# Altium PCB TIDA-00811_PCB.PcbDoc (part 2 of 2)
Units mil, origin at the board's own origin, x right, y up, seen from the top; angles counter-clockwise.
Board outline 2165.35 x 1968.5 mil, 2 copper layers (Top Layer, Bottom Layer), stack 62 mil thick; 184 components, 89 nets, 461 pads, 152 vias.
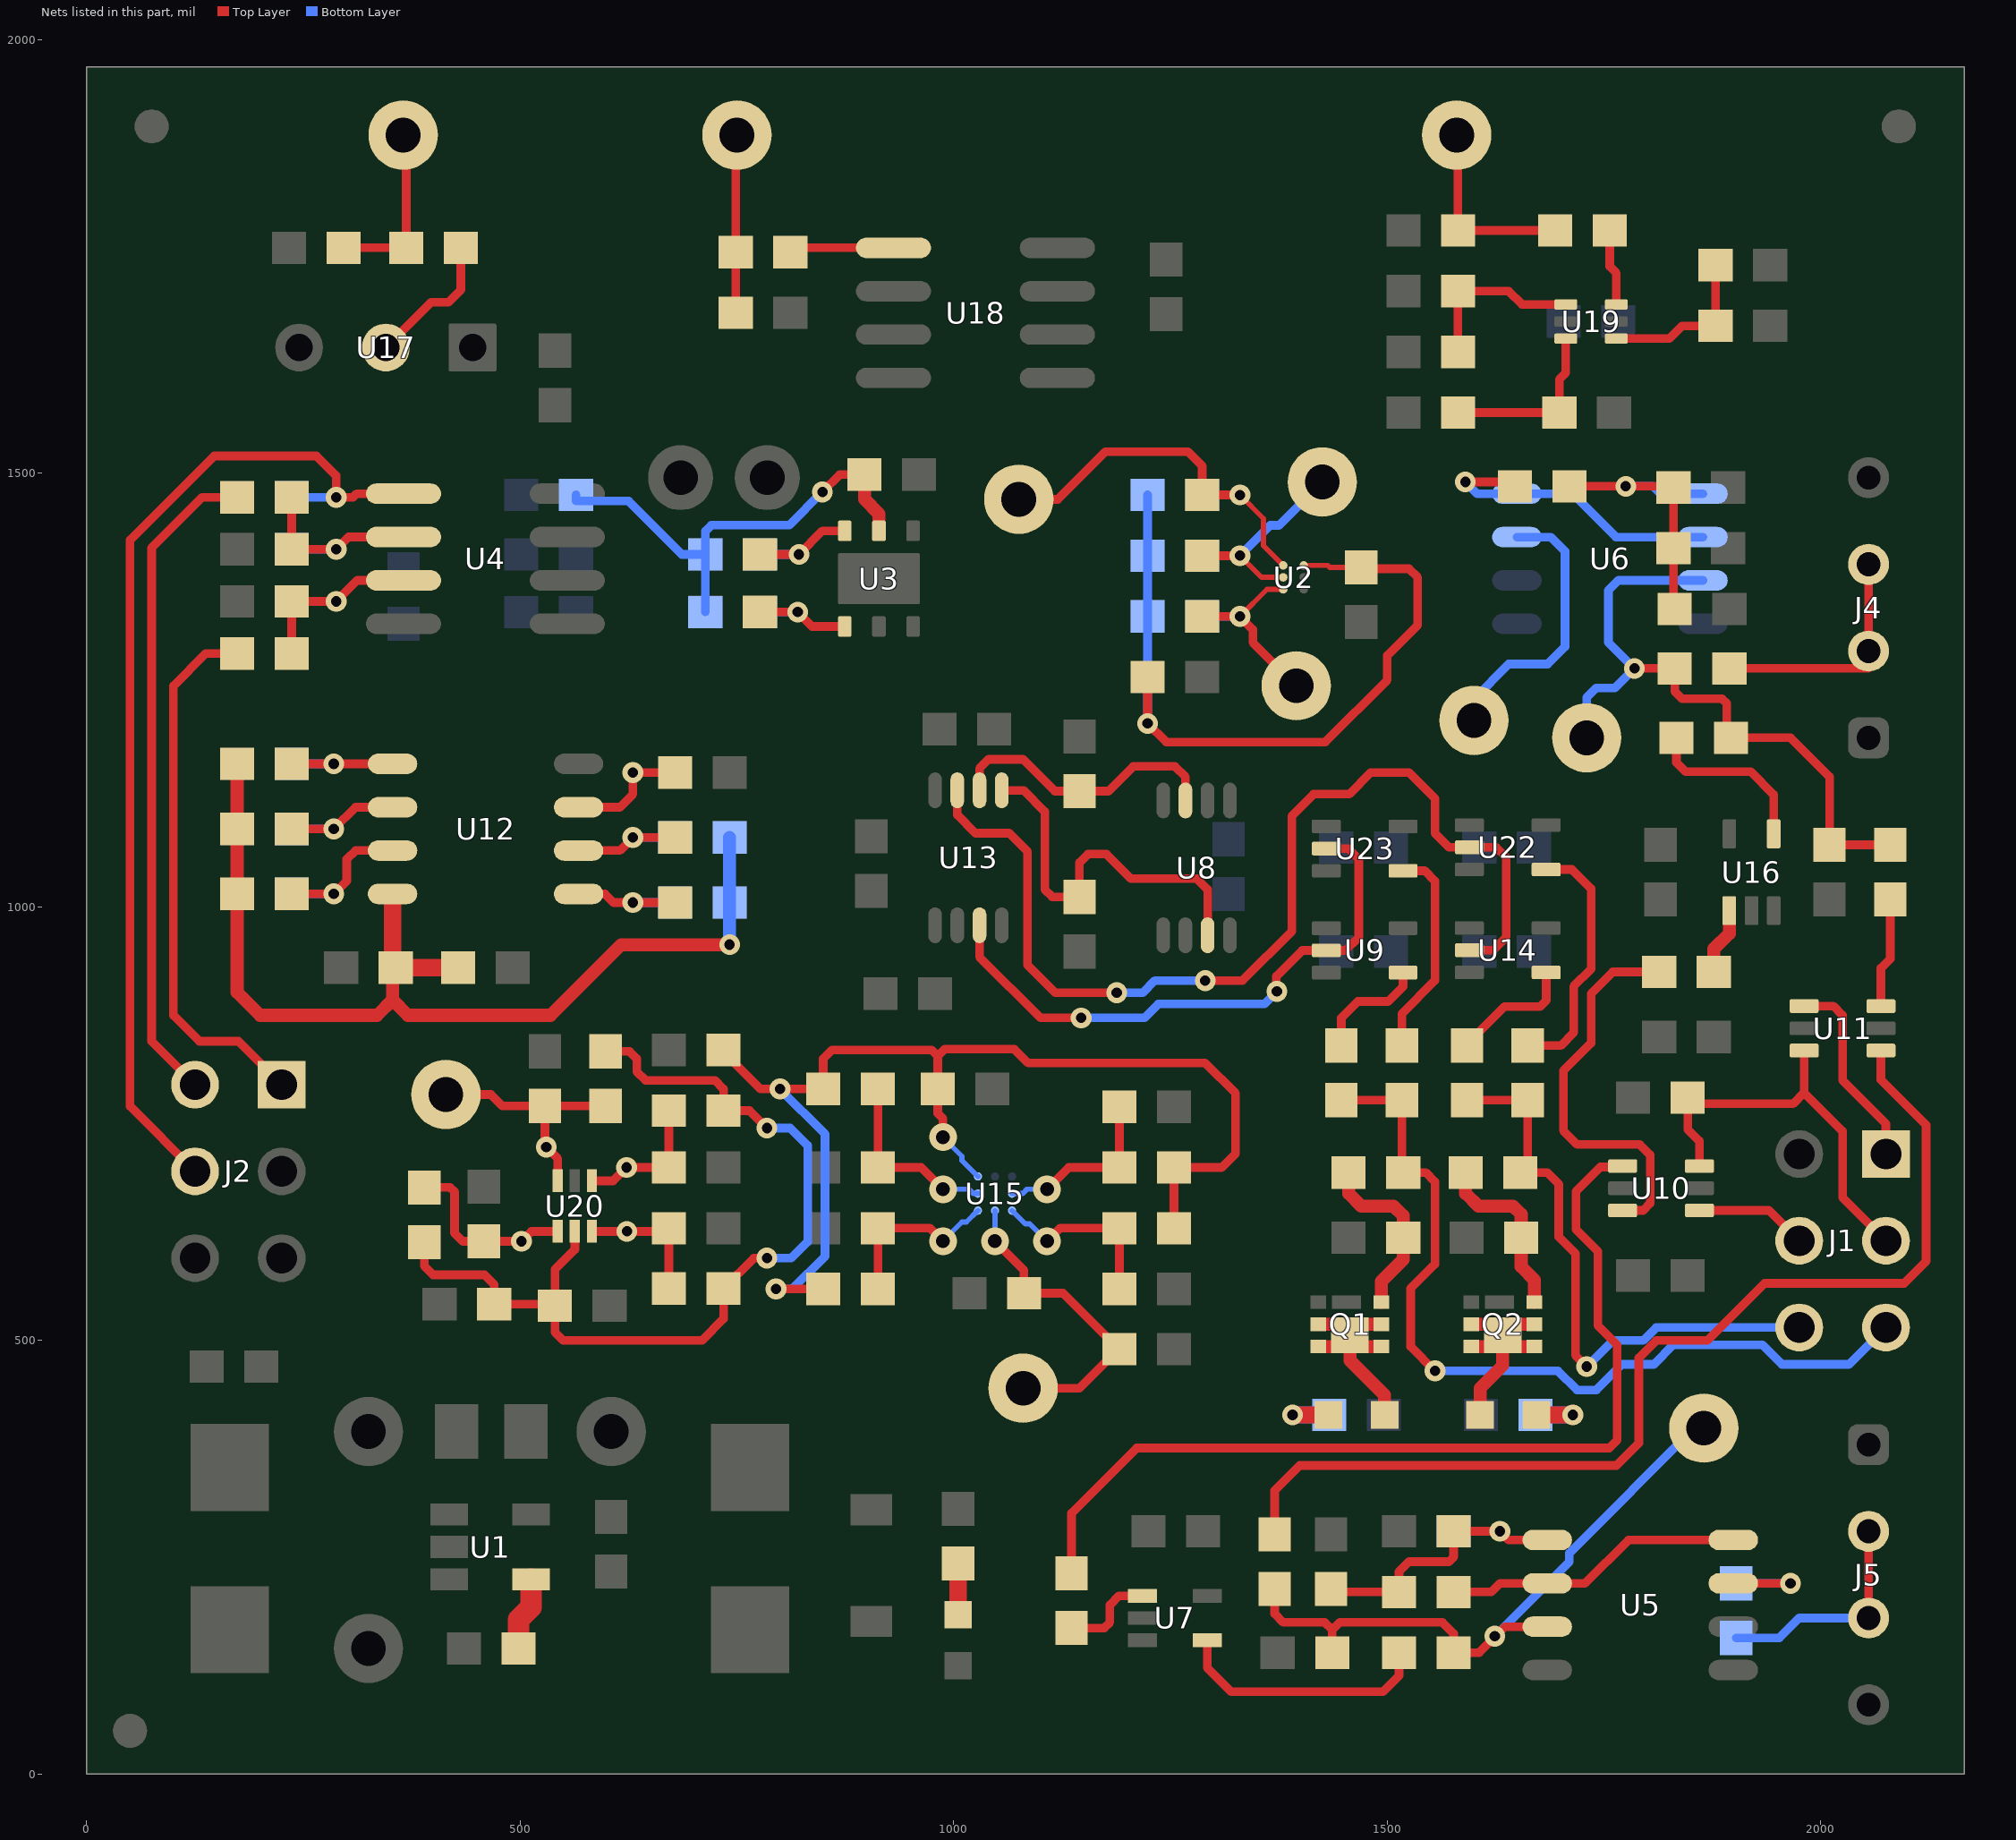
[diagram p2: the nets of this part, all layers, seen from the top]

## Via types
v1: diameter 24, hole 12, Top Layer to Bottom Layer, tented both sides, 140 vias
v2: diameter 32, hole 16, Top Layer to Bottom Layer, tented both sides, 8 vias
v3: diameter 19.68, hole 7.87, Top Layer to Bottom Layer, 4 vias

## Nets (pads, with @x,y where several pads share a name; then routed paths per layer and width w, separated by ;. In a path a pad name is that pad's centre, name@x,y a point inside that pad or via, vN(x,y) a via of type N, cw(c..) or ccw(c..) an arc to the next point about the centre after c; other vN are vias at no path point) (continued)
MCU_EN: J2.4 R3.1 U4.5 | length 1202
  Top Layer w10: J2.4@125,695 50,770 50,1423 147,1520 265,1520 287.77,1497.23 v1(287.77,1472.27) 307.27,1472.27 311.5,1476.5 U4.5@365.36,1476.5
  Bottom Layer w10: R3.1@236.51,1472.27 v1(287.77,1472.27)
MCU_INT: J1.5 R85.1 R109.2 R110.2 | length 1014
  Top Layer w10: R109.2@1446.88,777.17 R110.2@1516.88,777.17 1516.88,695.16 R85.1@1518.37,693.66 1544.34,693.66 1555,683 1555,588 1527,560 1527,493 v1(1555,465)
  Bottom Layer w10: v1(1555,465) 1696.82,465 1718.82,443 1741.18,443 1770.62,472.44 1807.44,472.44 1830,495 1932.44,495 1955,472.44 2032.44,472.44 J1.5@2075,515
MCU_INT1: J1.6 R86.1 R107.2 R108.2 | length 691.3
  Top Layer w10: R107.2@1591.88,777.17 R108.2@1661.88,777.17 R86.1@1661.88,695.16 ; R86.1@1651.88,695.16 R86.1@1653.37,693.66 1684.34,693.66 1697.69,680.32 1697.69,619.67 1717,600.35 1717,483 v1(1730,470)
  Bottom Layer w10: v1(1730,470) 1760,500 1795,500 1810,515 J1.6@1975,515
MCU_SCL: J2.1 R8.2 | length 627.1
  Top Layer w10: R8.2@173.52,1292.27 137.27,1292.27 100,1255 100,875 130,845 175,845 J2.1@225,795
MCU_SDA: J2.2 R9.2 | length 762.4
  Top Layer w10: J2.2@125,795 75,845 75,1414 133.27,1472.27 R9.2@173.52,1472.27
NetC5_2: C5.2 R20.1 R21.2 R22.2 R23.2 U2.C1 | length 902.1
  Top Layer w6: U2.C1@1403.62,1393.78 1431.22,1393.78 1433.5,1391.5 C5.2@1470,1391.5
  Top Layer w10: R20.1@1223.5,1265 v1(1223.5,1211.5) 1245,1190 1428.43,1190 1500,1261.57 1500,1290 1535,1325 1535,1380 1525,1390 1471.5,1390 C5.2@1470,1391.5
  Bottom Layer w10: v1(1223.5,1211.5) R21.2@1223.5,1335 R23.2@1223.5,1405 R22.2@1223.5,1475
NetC6_1: C6.1 U1.4 | length 85.5
  Top Layer w25: C6.1@498.16,145 498.16,178.16 512.4,192.4 U1.4@512.4,224.6
NetC7_2: C7.2 R15.2 R16.2 R77.1 U3.5 | length 557.4
  Top Layer w10: v1(848.5,1478.5) 868.5,1498.5 C7.2@897,1498.5
  Top Layer w15: C7.2@897,1498.5 897,1469.99 913.69,1453.3 U3.5@913.69,1433.61
  Bottom Layer w10: R77.1@564.34,1475 564.34,1468 625,1468 686.5,1406.5 R15.2@713.5,1406.5 ; R16.2@713.5,1340 R15.2@713.5,1406.5 ; v1(848.5,1478.5) 810.2,1440.2 720.2,1440.2 713.5,1433.5 R15.2@713.5,1406.5
NetC9_1: C9.1 C11.2 R10.1 R87.2 U5.1 | length 368.7
  Top Layer w10: C9.1@1435,213.5 1438.5,210 R10.1@1513.5,210 1513.5,233.5 1525,245 1571.2,245 1576.5,250.3 C11.2@1576.5,280 v1(1630,280) 1640,270 U5.1@1684.43,270
  Bottom Layer w10: R87.2@1576.5,280 v1(1630,280)
NetC10_1: C10.1 C12.2 R11.1 R88.2 U6.1 | length 353.8
  Top Layer w10: R11.1@1710,1485 v1(1775,1485) 1828.56,1485 R88.2@1830.02,1483.54 C12.2@1830.02,1413.54 1830.02,1345.04 C10.1@1831.51,1343.54
  Bottom Layer w10: v1(1775,1485) 1806.46,1485 1815,1476.46 U6.1@1864,1476.46
NetC18_2: C18.2 R28.1 R29.2 R30.2 R31.2 R32.2 R33.2 U12.8 | length 1214
  Top Layer w15: R31.2@173.5,1165 R30.2@173.5,1090 R29.2@173.5,1015 173.5,901.5 200,875 335,875 352.72,892.72 ; C18.2@352.72,933.78 352.72,892.72 ; v1(741.5,956.5) 616.5,956.5 535,875 370.43,875 352.72,892.72
  Top Layer w20: U12.8@352.72,1015 352.72,933.78 C18.2@356.5,930 R28.1@428.5,930
  Bottom Layer w15: v1(741.5,956.5) R33.2@741.5,1005 R32.2@741.5,1080
NetC23_2: C23.2 R53.2 R54.2 R68.2 R69.2 R70.1 U15.A3 | length 1390.1
  Top Layer w10: R70.1@735.03,831.94 776.97,790 v1(799.53,790) R53.2@849.54,790 849.54,825.01 859.54,835.01 974.52,835.01 981.53,828 ; v1(795.03,559.5) R54.2@849.54,559.5 ; v2(987.53,734.5) 987.53,756 981.53,762 C23.2@981.53,790 981.53,828 ; R69.2@1254.03,629.5 R68.2@1254.03,699.5 1309.03,699.5 1325,715.47 1325,758.08 ; 1325,780.92 1325,785 1290,820 1086,820 1070,836 989.53,836 981.53,828 ; 1325.03,758.11 1325.03,780.89
  Bottom Layer w6: v2(987.53,734.5) 1009.53,712.5 1009.53,707.5 U15.A3@1027.85,689.18
  Bottom Layer w10: v1(795.03,559.5) 814.03,559.5 851.53,597 851.53,738 v1(799.53,790)
NetC24_2: C24.2 R47.2 TP13.1 | length 203.5
  Top Layer w10: C24.2@296.5,1760 R47.2@368.5,1760 368.5,1886.5 TP13.1@365,1890
NetC26_2: C26.2 R48.2 TP14.1 | length 205.6
  Top Layer w10: C26.2@748.5,1685 R48.2@748.5,1755 748.5,1888.5 TP14.1@750,1890
NetC28_2: C28.2 R52.2 TP16.1 | length 222.6
  Top Layer w10: TP16.1@1580,1890 1581.5,1888.5 C28.2@1581.5,1780 R52.2@1693.5,1780
NetC29_1: C29.1 Q1.3 R85.2 | length 207.7
  Top Layer w15: R85.2@1455.38,693.66 1455.38,669.62 1470,655 1507.2,655 1518.37,643.83 C29.1@1518.37,618.66 1518.37,593.37 1493.2,568.2 Q1.3@1493.2,544.25
NetC30_1: C30.1 Q2.3 R86.2 | length 205.6
  Top Layer w15: R86.2@1590.38,693.66 1590.38,669.62 1605,655 1645,655 1654.4,645.6 C30.1@1654.4,618.66 1654.4,585.12 1669.52,570 Q2.3@1669.52,544.25
NetC31_2: C31.2 R90.1 R91.2 R94.2 R95.2 R98.2 U20.5 | length 1111.8
  Top Layer w10: R98.2@389.53,613.5 389.53,585.64 399.53,575.64 458.89,575.64 470.03,564.5 R90.1@470.03,541.94 538.1,541.94 C31.2@540.04,540 ; U20.5@563.03,625.87 563.03,605 540.04,582.01 C31.2@540.04,540 ; R91.2@598.53,833.44 626.09,833.44 634.53,825 634.53,809.85 644.38,800 724.53,800 734.53,790 R95.2@734.53,765 764.53,765 v1(784.53,745) ; v1(784.53,595) 769.53,595 R94.2@734.53,560 734.53,525 709.53,500 549.53,500 540.04,509.49 C31.2@540.04,540
  Bottom Layer w10: v1(784.53,595) 812.53,595 831.53,614 831.53,724.77 811.3,745 v1(784.53,745)
NetD2_1: D2.1 R1.1 | length 59
  Top Layer w20: D2.1@1005,184.06 R1.1@1005,243.03
NetD3_1: D3.1 Q1.1 Q1.2 Q1.5 Q1.6 Q1.8 | length 274.7
  Top Layer w15: Q1.6@1420.56,493.07 1444.08,493.07 Q1.8@1456.88,505.87 ; Q1.5@1420.56,518.66 1444.08,518.66 Q1.8@1456.88,505.87 ; Q1.1@1493.2,493.07 1469.67,493.07 Q1.8@1456.88,505.87 ; Q1.2@1493.2,518.66 1469.67,518.66 Q1.8@1456.88,505.87 ; D3.1@1496.9,414.25 1496.9,437.1 1456.88,477.12 Q1.8@1456.88,505.87
NetD3_2: D3.2 R83.1 | length 83.4
  Top Layer w20: v1(1390.75,414.25) D3.2@1431.94,414.25
  Bottom Layer w20: v1(1390.75,414.25) R83.1@1432.92,414.25
NetD4_1: D4.1 Q2.1 Q2.2 Q2.5 Q2.6 Q2.8 | length 264.5
  Top Layer w15: Q2.6@1596.88,493.07 1620.4,493.07 Q2.8@1633.2,505.87 ; Q2.5@1596.88,518.66 1620.4,518.66 Q2.8@1633.2,505.87 ; D4.1@1606.94,414.25 1606.94,444.94 1633.2,471.2 Q2.8@1633.2,495 ; Q2.1@1669.52,493.07 1635.13,493.07 Q2.8@1633.2,495 ; Q2.2@1669.52,518.66 1645.99,518.66 Q2.8@1633.2,505.87 ; Q2.8@1633.2,495 Q2.8@1633.2,505.87
NetD4_2: D4.2 R84.1 | length 83.4
  Top Layer w20: D4.2@1672.88,414.25 v1(1714.07,414.25)
  Bottom Layer w20: R84.1@1671.9,414.25 v1(1714.07,414.25)
NetJ4_2: J4.2 J4.3 R80.1 | length 260.5
  Top Layer w10: R80.1@1894.5,1275 2055,1275 J4.2@2055,1295 J4.3@2055,1375
NetJ5_2: J5.2 J5.3 R81.2 | length 262.2
  Top Layer w10: J5.3@2055,180 J5.2@2055,280
  Bottom Layer w10: R81.2@1902.28,157.01 1952.01,157.01 1975,180 J5.3@2055,180
NetR2_1: R2.1 U8.7 U13.5 | length 454.7
  Top Layer w10: U13.5@1055.28,1134.41 1080.59,1134.41 1105,1110 1105,1020 1113.5,1011.5 R2.1@1145,1011.5 1145,1051 1155,1061 1176,1061 1204.5,1032.5 1280.5,1032.5 1292.8,1020.2 U8.7@1292.8,967.24
NetR6_1: R6.1 R8.1 R73.1 U4.7 | length 250.1
  Top Layer w10: R8.1@236.51,1292.27 R73.1@236.51,1352.27 v1(287.77,1352.27) 312.01,1376.5 U4.7@365.36,1376.5
  Bottom Layer w10: R6.1@236.51,1352.27 v1(287.77,1352.27)
NetR7_1: R7.1 R9.1 R72.1 U4.6 | length 246
  Top Layer w10: R9.1@236.51,1472.27 R72.1@236.51,1412.27 v1(287.77,1412.27) 302.01,1426.5 U4.6@365.36,1426.5
  Bottom Layer w10: R7.1@236.51,1412.27 v1(287.77,1412.27)
NetR10_2: R10.2 U5.2 U5.8 | length 347.4
  Top Layer w10: R10.2@1576.5,210 1620,210 1630,220 U5.2@1684.43,220 1728,220 1778,270 U5.8@1899,270
NetR11_2: R11.2 U6.2 U6.8 | length 359.4
  Top Layer w10: v1(1590,1490) 1642.01,1490 R11.2@1647.01,1485
  Bottom Layer w10: v1(1590,1490) 1603.54,1476.46 U6.8@1649.43,1476.46 1713.54,1476.46 1763.54,1426.46 U6.2@1864,1426.46
NetR12_1: R12.1 R13.2 R14.2 TP11.1 U5.3 | length 766.7
  Top Layer w10: R14.2@1370,213.5 1370,185 1380,175 1427.99,175 1436.5,166.5 ; R12.1@1436.5,140 1436.5,166.5 ; U5.3@1684.43,170 1636,170 1606,140 R13.2@1576.5,140 1576.5,162.05 1563.54,175 1445,175 1436.5,166.5
  Bottom Layer w10: v1(1624,159) 1710,245 1710,255 1854,399 TP11.1@1865,399
NetR13_1: R13.1 U7.4 | length 298.5
  Top Layer w10: U7.4@1292.4,154.41 1292.4,122.6 1320,95 1495,95 1513.5,113.5 R13.1@1513.5,140
NetR15_1: R15.1 R17.1 U3.6 | length 154.1
  Top Layer w10: R17.1@776.5,1406.57 776.56,1406.5 v1(821.5,1406.5) 848.61,1433.61 U3.6@874.32,1433.61
  Bottom Layer w10: R15.1@776.5,1406.5 v1(821.5,1406.5)
NetR16_1: R16.1 R18.1 U3.1 | length 148.2
  Top Layer w10: R18.1@776.5,1340.07 776.56,1340 v1(820,1340) 836.62,1323.38 U3.1@874.32,1323.38
  Bottom Layer w10: R16.1@776.5,1340 v1(820,1340)
NetR19_2: R19.2 U8.3 U13.6 | length 326.1
  Top Layer w10: U13.6@1029.69,1134.41 1029.69,1159.69 1040.08,1170.08 1079.92,1170.08 1116.5,1133.5 R19.2@1145,1133.5 1178.5,1133.5 1207,1162 1255,1162 1267.2,1149.8 U8.3@1267.2,1122.76
NetR21_1: R21.1 R24.1 TP7.1 U2.A2 | length 256.9
  Top Layer w6: v1(1330,1335) 1361.22,1366.22 U2.A2@1380,1366.22
  Top Layer w10: R24.1@1286.5,1335 v1(1330,1335) 1345,1320 1345,1305 TP7.1@1395,1255
  Bottom Layer w10: R21.1@1286.5,1335 v1(1330,1335)
NetR22_1: R22.1 R25.1 TP5.1 U2.C2 | length 463.6
  Top Layer w6: v1(1330,1475) 1357.22,1447.78 1357.22,1416.56 U2.C2@1380,1393.78
  Top Layer w10: TP5.1@1075,1470 1120,1470 1175,1525 1270,1525 1286.5,1508.5 R25.1@1286.5,1475 v1(1330,1475)
  Bottom Layer w10: R22.1@1286.5,1475 v1(1330,1475)
NetR23_1: R23.1 R26.1 TP9.1 U2.B2 | length 277.6
  Top Layer w6: v1(1330,1405) 1355,1380 U2.B2@1380,1380
  Top Layer w10: R26.1@1286.5,1405 v1(1330,1405)
  Bottom Layer w10: R23.1@1286.5,1405 v1(1330,1405) 1365,1440 1375,1440 TP9.1@1425,1490
NetR29_1: R29.1 R34.1 U12.7 | length 200.1
  Top Layer w10: R29.1@236.5,1015 v1(285,1015) 300,1030 300,1055 310,1065 U12.7@352.72,1065
  Bottom Layer w10: R34.1@236.5,1015 v1(285,1015)
NetR30_1: R30.1 R35.1 U12.6 | length 175.1
  Top Layer w10: R30.1@236.5,1090 v1(285,1090) 310,1115 U12.6@352.72,1115
  Bottom Layer w10: R35.1@236.5,1090 v1(285,1090)
NetR31_1: R31.1 R39.1 U12.5 | length 164.7
  Top Layer w10: R31.1@236.5,1165 v1(285,1165) U12.5@352.72,1165
  Bottom Layer w10: R39.1@236.5,1165 v1(285,1165)
NetR32_1: R32.1 R41.1 U12.2 | length 165.9
  Top Layer w10: U12.2@567.28,1065 615,1065 v1(630,1080) R41.1@678.5,1080
  Bottom Layer w10: v1(630,1080) R32.1@678.5,1080
NetR33_1: R33.1 R40.1 U12.1 | length 163.9
  Top Layer w10: U12.1@567.28,1015 597.57,1015 607.57,1005 v1(630,1005) R40.1@678.5,1005
  Bottom Layer w10: v1(630,1005) R33.1@678.5,1005
NetR36_1: R36.1 R89.1 TP12.1 U15.C2 | length 376.3
  Top Layer w10: v2@1048.73,614.5 v2(1047.53,614.5) 1081.03,581 R89.1@1081.03,554.5 1126.03,554.5 1188.53,492 R36.1@1188.53,490 ; TP12.1@1080,445 1145,445 1188.53,488.53 R36.1@1188.53,490 ; R36.1@1191.03,490 R36.1@1188.53,490
  Bottom Layer w6: v2(1047.53,614.5) U15.C2@1047.53,649.82
NetR37_2: R37.2 R69.1 U15.C1 | length 214.7
  Top Layer w10: v2(1107.53,614.5) 1122.53,629.5 R69.1@1191.03,629.5 R37.2@1191.03,559.5
  Bottom Layer w6: U15.C1@1067.22,649.82 1082.53,634.5 1087.53,634.5 v2(1107.53,614.5)
NetR38_2: R38.2 R68.1 U15.B1 | length 208.5
  Top Layer w10: v2@1107.53,676.75 v2(1107.53,674.5) 1132.53,699.5 R68.1@1191.03,699.5 R38.2@1191.03,769.5
  Bottom Layer w6: U15.B1@1067.22,669.5 1079.53,669.5 1084.53,674.5 v2(1107.53,674.5)
NetR42_1: R42.1 U12.3 | length 142.4
  Top Layer w10: U12.3@567.28,1115 615,1115 630,1130 v1(630,1155) R42.1@678.5,1155
NetR43_1: R43.1 R45.2 R46.2 R80.2 TP10.1 U6.3 | length 790.7
  Top Layer w10: v1(1785,1275) R80.2@1831.51,1275 1831.51,1248.49 1840,1240 1886.27,1240 1891.5,1234.77 R45.2@1891.5,1205 ; R45.2@1896.5,1195 1965,1195 2010,1150 R43.1@2010,1071.5 R46.2@2080,1071.5
  Bottom Layer w10: TP10.1@1730,1185 TP10.1@1730,1195 1730,1241.63 1740.87,1252.5 1762.5,1252.5 v1(1785,1275) 1755,1305 1755,1365 1766.46,1376.46 U6.3@1864,1376.46
NetR44_1: R44.1 U16.1 | length 78.1
  Top Layer w15: R44.1@1876.5,925 1876.5,951.5 1894.41,969.41 U16.1@1894.41,995.71
NetR45_1: R45.1 U16.4 | length 211.1
  Top Layer w10: R45.1@1828.5,1195 R45.1@1828.5,1205 ; R45.1@1833.5,1195 1833.5,1166.5 1844,1156 1919,1156 1945.59,1129.41 U16.4@1945.59,1084.29
NetR47_1: R47.1 U17.2 | length 162.5
  Top Layer w10: U17.2@345,1645 397.17,1697.17 417.17,1697.17 431.5,1711.5 R47.1@431.5,1760
NetR48_1: R48.1 U18.1 | length 121.1
  Top Layer w10: R48.1@811.5,1755 816.5,1760 U18.1@930.51,1760
NetR49_1: R49.1 R55.2 U19.1 | length 190.5
  Top Layer w10: U19.1@1764.13,1655.31 1825.31,1655.31 1840,1670 R49.1@1878.5,1670 R55.2@1878.5,1740
NetR50_1: R50.1 R56.2 U19.6 | length 205.4
  Top Layer w10: R56.2@1581.5,1570 R50.1@1698.5,1570 1698.5,1608.5 1705.87,1615.87 U19.6@1705.87,1655.31
NetR51_1: R51.1 R59.2 U19.4 | length 200.7
  Top Layer w10: R59.2@1581.5,1640 R51.1@1581.5,1710 1640,1710 1655.31,1694.68 U19.4@1705.87,1694.68
NetR52_1: R52.1 U19.3 | length 87.3
  Top Layer w10: R52.1@1756.5,1780 1756.5,1738.5 1764.13,1730.87 U19.3@1764.13,1695.91
NetR53_1: R53.1 R57.2 U15.B3 | length 218.2
  Top Layer w10: R53.1@912.53,790 R57.2@912.53,699.5 962.53,699.5 v2(987.53,674.5)
  Bottom Layer w6: v2(987.53,674.5) 1017.53,674.5 1022.53,669.5 U15.B3@1027.85,669.5
NetR54_1: R54.1 R58.2 U15.C3 | length 206.2
  Top Layer w10: R54.1@912.53,559.5 R58.2@912.53,629.5 972.53,629.5 v2(987.53,614.5)
  Bottom Layer w6: v2(987.53,614.5) 1009.53,636.5 1014.53,636.5 U15.C3@1027.85,649.82
NetR65_1: R65.1 U7.1 | length 108.8
  Top Layer w10: R65.1@1135.91,168.5 1173.5,168.5 1180,175 1180,195 1190.59,205.59 U7.1@1217.6,205.59
NetR81_1: R81.1 U5.7 | length 128.7
  Top Layer w10: U5.7@1899,220 v1(1965,220)
  Bottom Layer w10: R81.1@1902.28,220 v1(1965,220)
NetR91_1: R91.1 R92.1 TP15.1 U20.3 | length 291.3
  Top Layer w10: TP15.1@420.81,777.18 TP15.1@414.31,783.67 466.3,783.67 479.53,770.45 R92.1@528.53,770.45 ; U20.3@543.35,684.13 543.35,709.68 528.53,724.5 R92.1@528.53,770.45 ; R91.1@598.53,770.45 R92.1@528.53,770.45
  other v1: 530.11,723.06
NetR93_1: R93.1 R98.1 U20.4 | length 212.1
  Top Layer w10: R98.1@389.53,676.5 419.3,676.5 424.33,671.46 424.33,623.9 433.82,614.41 R93.1@458.03,614.41 v1(501.44,614.41) 512.9,625.87 U20.4@543.35,625.87
NetR94_1: R94.1 R97.1 U20.6 | length 159.7
  Top Layer w10: U20.6@582.72,625.87 v1(623.03,625.87) 667.97,625.87 R97.1@671.54,629.43 R94.1@671.54,560
NetR95_1: R95.1 R96.1 U20.1 | length 160.8
  Top Layer w10: U20.1@582.72,684.13 607.17,684.13 622.53,699.5 R96.1@671.54,699.5 R95.1@671.54,765
  Bottom Layer w10: v1@622.53,699.5 v1(622.6,699.57)
NetR107_1: R107.1 U14.4 | length 146.1
  Top Layer w10: R107.1@1591.88,840.16 1591.88,841.88 1635,885 1676,885 1683.18,892.18 U14.4@1683.18,924.45
NetR108_1: R108.1 U22.4 | length 294.5
  Top Layer w10: R108.1@1661.88,840.16 1700.16,840.16 1715,855 1715,908.28 1735,928.28 1735,1021 1712.85,1043.15 U22.4@1683.18,1043.15
NetR109_1: R109.1 U9.4 | length 134.1
  Top Layer w10: R109.1@1446.88,840.16 1446.88,871.88 1466,891 1501,891 1518.18,908.18 U9.4@1518.18,924.25
NetR110_1: R110.1 U23.4 | length 247.3
  Top Layer w10: R110.1@1516.88,840.16 1516.88,876.88 1555,915 1555,1030 1543.35,1041.65 U23.4@1518.18,1041.65
NetTP8_1: TP8.1 U6.7 | length 302.2
  Bottom Layer w10: TP8.1@1600,1240 1640,1280 1685,1280 1705,1300 1705,1410 1688.54,1426.46 U6.7@1649.43,1426.46
NetU9_2: U9.2 U13.3 U23.2 | length 685.2
  Top Layer w10: U13.3@1029.69,978.9 1029.69,942.31 1100,872 v1(1147,872) ; v1(1372.72,902.58) 1372,903.31 1372,920 1401.84,949.84 U9.2@1429.6,949.84 1451.84,949.84 1467,965 1467,1055 1454.76,1067.24 U23.2@1429.6,1067.24
  Bottom Layer w10: v1(1147,872) 1220,872 1236,888 1358.14,888 v1(1372.72,902.58)
NetU13_7: U13.7 U14.2 U22.2 | length 1211
  Top Layer w10: U13.7@1004.09,1134.41 1004.09,1105.91 1025,1085 1063.9,1085 1085,1063.9 1085,933 1117,901 v1(1188,901) ; v1(1290,915) 1333,915 1389.99,971.99 1389.99,1104.99 1415,1130 1456,1130 1481,1155 1525,1155 1555,1125 1555,1085 1571.26,1068.74 U22.2@1594.6,1068.74 1625.74,1068.74 1637,1057.48 1637,965 1622.04,950.04 U14.2@1594.6,950.04
  Bottom Layer w10: v1(1188,901) 1218,901 1232,915 v1(1290,915)
RXD: J1.1 U11.4 | length 229.4
  Top Layer w10: U11.4@1980.71,885.59 2014.41,885.59 2025,875 2025,800 2075,750 J1.1@2075,715
RXD1: R14.1 U11.1 | length 1233.6
  Top Layer w10: R14.1@1370,276.5 1370,327 1399,356 1764.28,356 1790,381.72 1790,480 1810,500 1869,500 1935,566 2096,566 2121.35,591.35 2121.35,748.65 2069.29,800.71 U11.1@2069.29,834.41
RXD2: R46.1 U11.3 | length 127.3
  Top Layer w10: U11.3@2069.29,885.59 2069.29,929.29 2080,940 R46.1@2080,1008.5
TXD: J1.4 U10.4 | length 129.5
  Top Layer w10: U10.4@1860,650 1940,650 J1.4@1975,615
TXD1: R65.2 U10.1 | length 1105.8
  Top Layer w10: R65.2@1135.91,231.5 1135.91,300.91 1211,376 1756,376 1765,385 1765,495 1743,517 1743,602.64 1717.69,627.95 1717.69,672.05 1745.64,700 1770.24,700 U10.1@1771.42,701.18
TXD2: R44.2 U10.3 | length 462.9
  Top Layer w10: U10.3@1771.42,650 1795,650 1803.15,658.15 1803.15,714.12 1791.26,726 1719,726 1703,742 1703,811 1735,843 1735,900 1760,925 R44.2@1813.5,925
UART_CTRL: J1.3 R27.2 U10.6 U11.6 | length 482.4
  Top Layer w10: R27.2@1846.5,780 R27.2@1846.5,773 ; U10.6@1860,701.18 1860,730 1846.5,743.5 R27.2@1846.5,773 ; U11.6@1980.71,834.41 1980.71,785.71 ; J1.3@2075,615 2025,665 2025,741.42 1980.71,785.71 ; R27.2@1846.5,773 1968,773 1980.71,785.71
pads on no net: FID1.1 FID2.1 FID3.1 FID4.1 FID5.1 FID6.1 J2.3 U2. U3.3 U3.4 U3.7@888.89,1378.5 U3.7@938.5,1378.5 U4.1 U9.1 U14.1 U18.2 U18.3 U18.5 U18.6 U18.7 U22.1 U23.1

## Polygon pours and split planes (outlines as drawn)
DC_IN on Top Layer "DC_IN_L01_P002" (solid, remove dead copper, pour order 2): 100.3,399.7 100.3,314.7 110.3,304.7 235.3,304.7 250.3,289.7 430.3,289.7 445.3,304.7 445.3,434.7 435.3,444.7 284.7,444.7 249.7,409.7 110.3,409.7
GND on Bottom Layer "GND_L02_P000" (solid, remove dead copper, pour order 0): 35,1940 35,150 135,50 300,50 2040,50 2125.26,135.26 2125.26,1060 2124.41,1925.6 2109.99,1940

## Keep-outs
Keep-Out Layer:
  lines w8: 25,26 2140.35,26 2140.35,1009.65 2140.35,1550 2140.35,1950 25,1950 25,26

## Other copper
Top Layer:
  text ".Layer_Name" at 523.85,-858.49 h60
Bottom Layer:
  region net GND: 1039.53,677.5 1039.53,662.5 1054.53,662.5 1054.53,677.5
  pour cut-out: 1192.53,529.5 902.53,529.5 902.53,819.5 1027.53,819.5 1027.53,779.5 942.53,779.5 942.53,569.5 1152.53,569.5 1152.53,779.5 1077.53,779.5 1077.53,819.5 1192.53,819.5
  text ".Layer_Name" at 523.85,-858.49 h60
Multi-Layer:
  pour cut-out: 1091.02,628.04 1091.02,718.04 1001.02,718.04 1001.02,628.04

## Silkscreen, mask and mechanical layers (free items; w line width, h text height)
Top Overlay:
  circle w10: c1418,1367 r2.24
  circle w10: c1217,232 r5.1
  circle w10: c375.39,300 r5.39
  circle w10: c583,713 r2.24
  lines w6: 462,861 475,861 485.23,850.77 485.23,850 485.23,700 ; 481.64,705 482.31,705 ; 1285,824 1285,873 1300,888 1591,888 1594,885 1594,868.64 ; 1296,727 1410,727 1415,732 1590,732 1596,738 1596,748.68 ; 1310,873 1385,873 ; 1385,873 1385,872 1378,865 1378,880 1385,873
  text "A" at 1421,359 h30
  text "K" at 1488,359 h30
  text "A" at 1664,355 h30
  text "K" at 1596,354 h30
  text ".Layer_Name" at 523.85,-858.49 h60
Bottom Overlay:
  circle w10: c1088.53,690 r1.41
  lines w6: 1016.7,638.67 1016.7,700.33 1078.36,700.33 1078.36,638.67 1016.7,638.67
  text "'.PRJ_Number'-.PCB_Rev" at 845,60 h108.27 r270
  text ".Layer_Name" at 523.85,-858.49 h60
Top Paste:
  text ".Layer_Name" at 523.85,-858.49 h60
Bottom Paste:
  text ".Layer_Name" at 523.85,-858.49 h60
Top Solder:
  text ".Layer_Name" at 523.85,-858.49 h60
  text ".Layer_Name" at 523.85,-858.49 h60
Bottom Solder:
  text ".Layer_Name" at 523.85,-858.49 h60
M1 Board Outline:
  lines w10: 0,0 2165.35,0 2165.35,1968.5 1574.8,1968.5 0,1968.5 0,0
M2 Board Dimensions:
  rectangle: 71.85,-400 446.85,-275
  rectangle: -53.15,-275 71.85,-150
  lines w7: -53.15,-275 946.85,-275 ; 71.85,-400 71.85,-150 ; 196.85,-400 196.85,-150 ; 446.85,-400 446.85,-150 ; 696.85,-400 696.85,-150 ; -53.15,-400 -53.15,-150 946.85,-150 946.85,-400 -53.15,-400
  text "M1 Board Outline" at 523.85,-858.49 h60
M3 3D STEP Top:
  text ".Layer_Name" at 523.85,-858.49 h60
M4 3D STEP Bottom:
  text ".Layer_Name" at 523.85,-858.49 h60
M5 Assembly Top:
  circle w10: c930,1774 r4.47
  circle w10: c455,1692 r6.26
  circle w10: c1895,975 r5
  circle w10: c1575,975 r5
  circle w10: c1575,1095 r5
  circle w10: c1410,975 r5
  circle w10: c1410,1095 r5
  circle w10: c388.39,297 r3.61
  circle w10: c225,795 r14.14
  circle w10: c2075,715 r14.14
  circle w10: c2055,1195 r14.14
  circle w10: c2055,380 r14.14
  circle w10: c1191.39,205 r3.61
  lines w8: 989.57,1783.43 989.57,1586.57 1060.43,1586.57 1060.43,1783.43 991,1783.43
  lines w10: -345.15,-930.17 6254.85,-930.17 ; -345.15,-726.83 6256.85,-726.83 ; -345.15,-523.5 -345.15,-1133.5 3659.85,-1133.5 6256.85,-1133.5 6256.85,-523.5 -344.65,-523.5 -344.65,-1133.5 1230.85,-1133.5 ; 2119.85,-1133.5 2119.85,-523.5 ; 3386.85,-726.83 3386.85,-523.5 ; 4226.85,-726.83 4226.85,-523.5 ; 4848.85,-1140 4848.85,-937.17
  text "COMPONENTS MARKED 'DNP' SHOULD NOT BE POPULATED." at 1100.35,-318.5 h60
  text "ASSEMBLY VARIANT:" at 1099.85,-434 h60
  text ".VariantName" at 2135.85,-434 h60
  text ".PRJ_Number" at 2605,-655 h35
  text "PCB VIEWED FROM TOP SIDE" at -281.65,-655.67 h60
  text "REV:" at 3584.85,-655.67 h60
  text ".PCB_Rev" at 3876.35,-655.67 h60
  text "SVN REV:" at 4422.85,-655.67 h60
  text ".VersionControl_RevNumber" at 4928.85,-655.67 h60
  text "BOARD #:" at 2150,-665 h60
  text ".TID" at 2640,-855 h60
  text "LAYER NAME =" at -282.65,-857.49 h60
  text "TID #:" at 2194.85,-859 h60
  text ".Layer_Name" at 511,-886 h60
  text "PLOT NAME =" at -281.65,-1064.34 h60
  text ".plot_File_Name" at 523.85,-1064.34 h60
  text "GENERATED    :" at 2196.85,-1064.34 h60
  text ".Print_Date" at 3066.35,-1064.34 h60
  text ".Print_Time" at 3795.35,-1064.34 h60
  text "TEXAS INSTRUMENTS" at 5059.85,-1064.34 h60
M6 Assembly Bottom:
  lines w10: -345.65,-727.33 6256.35,-727.33 ; -343.65,-930.67 6256.35,-930.67 ; 1062.35,-1140.5 1062.35,-937.67 ; 1684.35,-727.33 1684.35,-524 ; 2524.35,-727.33 2524.35,-524 ; 3791.35,-1134 3791.35,-524 ; 4680.35,-1134 6255.85,-1134 6255.85,-524 -345.65,-524 -345.65,-1134 2251.35,-1134 6256.35,-1134 6256.35,-524
  text "COMPONENTS MARKED 'DNP' SHOULD NOT BE POPULATED." at 6048.85,-318 h60
  text ".VariantName" at 5004.85,-434 h60
  text "ASSEMBLY VARIANT:" at 6043.85,-434 h60
  text ".PRJ_Number" at 3310,-650 h35
  text ".VersionControl_RevNumber" at 982.35,-656.17 h60
  text "SVN REV:" at 1488.35,-656.17 h60
  text ".PCB_Rev" at 2034.85,-656.17 h60
  text "REV:" at 2326.35,-656.17 h60
  text "PCB VIEWED FROM BOTTOM SIDE" at 6192.85,-656.17 h60
  text "BOARD #:" at 3755,-660 h60
  text ".TID" at 3170.85,-859.5 h60
  text "TID #:" at 3716.35,-859.5 h60
  text ".Layer_Name" at 5186.85,-863 h60
  text "LAYER NAME =" at 6005.85,-868 h60
  text "TEXAS INSTRUMENTS" at 851.35,-1064.84 h60
  text ".Print_Time" at 2115.85,-1064.84 h60
  text ".Print_Date" at 2844.85,-1064.84 h60
  text "GENERATED    :" at 3714.35,-1064.84 h60
  text ".plot_File_Name" at 5387.35,-1064.84 h60
  text "PLOT NAME =" at 6192.85,-1064.84 h60
M9 Title Sheet:
  drawing of 57 lines, arcs and shapes, not listed
  text "1" at 686.69,8036.5 h70
  text "2" at 3182.35,8036.5 h70
  text "3" at 5671.69,8036.5 h70
  text "4" at 8178.36,8036.5 h70
  text "5" at 10677.35,8036.5 h70
  text "6" at 13182.35,8036.5 h70
  text "A" at -469.65,6893.5 h70
  text "A" at 14330.35,6893.5 h70
  text "B" at -469.65,4513.5 h70
  text "B" at 14330.35,4513.5 h70
  text "C" at -469.65,2138.5 h70
  text "C" at 14330.35,2138.5 h70
  text "PROJECT TITLE:" at 11290.35,277.5 h45
  text ".PRJ_Title" at 11340.35,144.17 h70
  text "DESIGNED FOR:" at 11290.35,-23.5 h45
  text ".PRJ_Customer" at 11340.35,-163.5 h70
  text "D" at -469.65,-231.5 h70
  text "D" at 14330.35,-231.5 h70
  text "FILE NAME:" at 11290.35,-323.5 h45
  text ".PCB_File_Name_No_Path" at 11340.35,-443.5 h70
  text "Texas Instruments (TI) and/or its licensors do not warrant the accuracy or completeness of this specification" at 6320.85,-605.34 h45
  text "ENGINEER:" at 11290.35,-613.5 h45
  text "LAYOUT BY:" at 12795.35,-613.5 h45
  text "or any information contained therein. TI and/or its licensors do not warrant that this design will meet" at 6275.86,-718 h45
  text ".PRJ_Engineer" at 11340.35,-768.49 h70
  text ".PCB_Layout" at 12845.85,-768.49 h70
  text "the specifications, will be suitable for your application or fit for any particular purpose, or will operate in" at 6275.86,-830.67 h45
  text "ALTIUM DESIGNER VERSION:" at 12795.35,-923.5 h45
  text "an implementation. TI and/or its licensors do not warrant that the design is production worthy. You should" at 6275.86,-943.33 h45
  text "completely validate and test your design implementation to confirm the system functionality for your application." at 6320.85,-1056 h45
  text ".print_Scale" at 11340.35,-1056.83 h70
  text ".Application_BuildNumber" at 12845.85,-1056.83 h70
  text "1" at 686.69,-1263.5 h70
  text "2" at 3182.35,-1263.5 h70
  text "3" at 5671.69,-1263.5 h70
  text "4" at 8178.36,-1263.5 h70
  text "5" at 10677.35,-1263.5 h70
  text "6" at 13182.35,-1263.5 h70
M10 Fab Notes:
  drawing of 189 lines, arcs and shapes, not listed
  text "DESIGN INFORMATION" at 12324.87,6201 h60
  text "MIL" at 12971.85,6029 h60
  text "MIN. TRACK WIDTH:" at 11680.31,6021 h60
  text "6" at 12736.85,6020 h60
  text "6.862" at 12665,5893 h60
  text "MIN. CLEARANCE:" at 11680.31,5889 h60
  text "MIL" at 12974.85,5888 h60
  text "MIN. VIA PAD SIZE:" at 11680.31,5757 h60
  text "MIL" at 12975.85,5757 h60
  text "19.685" at 12608.85,5756 h60
  text "0.15mm (5.9055MIL)" at 12375.31,5615.29 h60
  text "EXTERNAL" at 13246,5612 h60
  text "MINIMUM ANNULAR RING" at 11351.08,5611 h60
  text "PER" at 11551.08,5493 h60
  text "IPC-D-275 CLASS 2 LEVEL C" at 11771.08,5493 h60
  text "MIL, HOLES" at 13259.31,5380.71 h60
  text "+/-" at 12866.85,5380 h60
  text "+/-" at 13720.85,5380 h60
  text "REGISTRATION TOLERANCES:" at 11351.08,5375 h60
  text "METAL" at 12550.85,5375 h60
  text "5" at 13127.05,5375 h60
  text "3" at 13960.05,5375 h60
  text "MIL" at 14076.31,5375 h60
  text "+/-" at 13720.85,5262 h60
  text "HOLE SIZE TOLERANCE (UNLESS OTHERWISE SPECIFIED):" at 11351.08,5257 h60
  text "3" at 13960.05,5257 h60
  text "MIL" at 14076.31,5257 h60
  text "MATERIAL:" at 11276.31,5047.54 h60
  text "FR-4 High Tg" at 12262.75,4907.21 h60
  text "FR-408" at 11697.31,4898.64 h60
  text "OTHER" at 13185.31,4898.64 h60
  text "X" at 12107.85,4895 h60
  text "63 MIL (1.6mm) +/-10%" at 12017.41,4735.92 h60
  text "THICKNESS:" at 11351.08,4731.64 h60
  text "X" at 11889.25,4731.64 h60
  text "OTHER" at 13302.31,4731.64 h60
  text "TOLERANCE:" at 11351.08,4573.64 h60
  text "X" at 12190.38,4573.64 h60
  text "ANSI IPC-6012 TYPE 3 CLASS 2" at 12377.33,4573.64 h60
  text "OTHER +/-" at 12377.31,4417.64 h60
  text "BOW & TWIST:" at 11351.08,4260.64 h60
  text "X" at 12190.38,4260.64 h60
  text "ANSI IPC-6012 TYPE 3 CLASS 2" at 12377.33,4260.64 h60
  text "OTHER +/-" at 12377.31,4102.13 h60
  text "DRILLING:" at 11276.31,3963.64 h60
  text "REFERENCE:" at 11351.08,3846.64 h60
  text "X" at 11999.31,3846.64 h60
  text "AS SHOWN" at 12186.31,3846.64 h60
  text "X" at 12900.31,3846.64 h60
  text "NC_DRILL FILES" at 13037.31,3846.64 h60
  text "PTH COPPER THICKNESS:" at 11351.08,3688.64 h60
  text "X" at 12481.31,3688.64 h60
  text "20-30 um" at 12618.31,3688.64 h60
  text "OTHER" at 13335.31,3688.64 h60
  text "BOARD FINISH:" at 11276.31,3529.64 h60
  text "SILKSCREEN:" at 11431.53,3411.64 h60
  text "X" at 12380.31,3411.64 h60
  text "TOP" at 12506.31,3411.64 h60
  text "X" at 12890.31,3411.64 h60
  text "BOTTOM" at 13017.31,3411.64 h60
  text "SILKSCREEN COLOR:" at 11431.53,3244.64 h60
  text "X" at 12379.27,3244.64 h60
  text "WHITE" at 12506.31,3244.64 h60
  text "OTHER" at 13017.31,3244.64 h60
  text "X" at 12510.27,3085.44 h60
  text "GREEN" at 12637.31,3085.44 h60
  text "OTHER" at 13255.31,3085.44 h60
  text "SOLDER RESIST COLOR:" at 11431.53,3074.64 h60
  text "X" at 12510.27,2915.44 h60
  text "MATTE" at 12637.31,2915.44 h60
  text "SEMI-GLOSS" at 13254.85,2914.8 h60
  text "IMMERSION GOLD (ENIG)" at 12337.31,2726.92 h60
  text "ENEPIG" at 13674.85,2723.64 h60
  text "SURFACE FINISH:" at 11276.31,2722.64 h60
  text "X" at 12150.36,2722.64 h60
  text "IMM. TIN/SILVER OR EQUIV" at 11605.85,2565.64 h60
  text "OTHER" at 13037.31,2565.64 h60
  text "ARRAY/PANEL:" at 11276.31,2386.64 h60
  text "CUT AND TRIM PER M1 BOARD OUTLINE" at 12337.31,2382.35 h60
  text "N.C. ROUTE" at 12337.31,2230.64 h60
  text "X" at 13016.31,2230.64 h60
  text "V. SCORE" at 13203.31,2230.64 h60
  text "CERTIFICATION:" at 11276.31,2093.64 h60
  text "MATERIALS AND WORKMANSHIP FOR ALL PCBS" at 12001.31,2093.64 h60
  text "TO MEET OR EXCEED THE REQUIREMENTS OF:" at 12001.31,1995.64 h60
  text "X" at 11627.81,1859.13 h60
  text "ANSI IPC-A-600F CLASS ->" at 11766.81,1859.13 h60
  text "X" at 13405.87,1859.13 h60
  text "2" at 13524.81,1859.14 h60
  text "1" at 13209.81,1857.64 h60
  text "3" at 13878.81,1857.64 h60
  text "X" at 12441.87,1699.64 h60
  text "RoHS" at 12578.81,1699.64 h60
  text "OTHER" at 13223.21,1699.64 h60
  text "PER ORDER" at 13620.27,1699.64 h60
  text "ALL BOARDS MUST MEET OR EXCEED UL94-V0 REQUIREMENTS." at 11303.85,1534 h60
  text "PCB MUST BEAR THE UL94V-0 UL REGISTERED MATERIAL ID NUMBER" at 11303.85,1414 h60
  text "VIA TENTING:" at 12452.85,1263 h60
  text "X" at 13212.85,1261 h60
  text "YES" at 13002.52,1253.92 h60
  text "NO" at 13367.32,1248.69 h60
  text "ADDITIONAL REQUIREMENTS:" at 11276.31,1240.64 h60
  text "IMPEDANCE CONTROL:" at 12474.85,1134 h60
  text "YES" at 13458.85,1133 h60
  text "MICROSECTION:" at 11351.08,1125.64 h60
  text "YES" at 12256.81,1125.64 h60
  text "X" at 14000.85,1126 h60
  text "NO" at 13834.32,1115.69 h60
  text "REQUIRED" at 13118.31,969.49 h60
  text "BARE BOARD ELEC. TEST:" at 11351.08,966.64 h60
  text "NONE" at 12656.81,966.64 h60
  text "X" at 12991.31,966.64 h60
  text "PER ORDER" at 13710.31,966.64 h60
M11 Gerber Information:
  lines w10: -345.15,-930.17 6254.85,-930.17 ; -345.15,-726.83 6256.85,-726.83 ; -345.15,-523.5 -345.15,-1133.5 3659.85,-1133.5 6256.85,-1133.5 6256.85,-523.5 -344.65,-523.5 -344.65,-1133.5 1230.85,-1133.5 ; 2119.85,-1133.5 2119.85,-523.5 ; 3386.85,-726.83 3386.85,-523.5 ; 4226.85,-726.83 4226.85,-523.5 ; 4848.85,-1140 4848.85,-937.17
  text ".PRJ_Number" at 2605,-655 h35
  text "ALL ARTWORK VIEWED FROM TOP SIDE" at -281.65,-655.67 h60
  text "REV:" at 3584.85,-655.67 h60
  text ".PCB_Rev" at 3876.35,-655.67 h60
  text "SVN REV:" at 4422.85,-655.67 h60
  text ".VersionControl_RevNumber" at 4928.85,-655.67 h60
  text "BOARD #:" at 2150,-665 h60
  text ".TID" at 2640,-855 h60
  text "LAYER NAME =" at -281.65,-858.49 h60
  text "TID #:" at 2194.85,-859 h60
  text ".plot_File_Name" at 391,-1057 h40
  text "PLOT NAME =" at -281.65,-1064.34 h60
  text "GENERATED    :" at 2196.85,-1064.34 h60
  text ".Print_Date" at 3066.35,-1064.34 h60
  text ".Print_Time" at 3795.35,-1064.34 h60
  text "TEXAS INSTRUMENTS" at 5059.85,-1064.34 h60
M12 Stackup:
  drawing of 191 lines, arcs and shapes, not listed
  text "Layer" at 9737.19,7830 h60
  text "Name" at 10147.11,7830 h60
  text "Material" at 11076.85,7830 h60
  text "Thickness" at 11936.62,7830 h60
  text "Constant" at 12586.45,7830 h60
  text "Board Layer Stack" at 13156.31,7830 h60
  text "1" at 9737.19,7710 h60
  text "Top Overlay" at 10147.11,7710 h60
  text "2" at 9737.19,7590 h60
  text "Top Solder" at 10147.11,7590 h60
  text "Solder Resist" at 11076.85,7590 h60
  text "0.40mil" at 11936.62,7590 h60
  text "3.5" at 12586.45,7590 h60
  text "3" at 9737.19,7470 h60
  text "Top Layer" at 10147.11,7470 h60
  text "Copper" at 11076.85,7470 h60
  text "1.40mil" at 11936.62,7470 h60
  text "4" at 9737.19,7350 h60
  text "Dielectric1" at 10147.11,7350 h60
  text "FR-4 High Tg" at 11076.85,7350 h60
  text "59.20mil" at 11936.62,7350 h60
  text "4.8" at 12586.45,7350 h60
  text "5" at 9737.19,7230 h60
  text "Bottom Layer" at 10147.11,7230 h60
  text "Copper" at 11076.85,7230 h60
  text "1.40mil" at 11936.62,7230 h60
  text "6" at 9737.19,7110 h60
  text "Bottom Solder" at 10147.11,7110 h60
  text "Solder Resist" at 11076.85,7110 h60
  text "0.40mil" at 11936.62,7110 h60
  text "3.5" at 12586.45,7110 h60
  text "7" at 9737.19,6990 h60
  text "Bottom Overlay" at 10147.11,6990 h60
M13 Component Bodies Top:
  text ".Layer_Name" at 523.85,-858.49 h60
M14 Component Bodies Bottom:
  text ".Layer_Name" at 523.85,-858.49 h60
M15 Courtyards Top:
  text ".Layer_Name" at 523.85,-858.49 h60
M16 Courtyards Bottom:
  text ".Layer_Name" at 523.85,-858.49 h60
Drill Drawing:
  circle w10: c2930.82,1109.02 r16.6
  circle w10: c2930.82,1109.02 r27.67
  circle w10: c2930.82,611.02 r27.67
  lines w10: 2903.16,763.18 2958.49,763.18 2930.82,707.85 2903.16,763.18 ; 2903.16,832.35 2930.82,846.18 2958.49,832.35 2944.66,860.02 2958.49,887.68 2930.82,873.85 2903.16,887.68 2916.99,860.02 2903.16,832.35 ; 2903.16,956.85 2958.49,956.85 2958.49,1012.18 2903.16,1012.18 2903.16,956.85 ; 2903.16,1219.68 2916.99,1219.68 2930.82,1205.85 2944.66,1219.68 2958.49,1219.68 2944.66,1233.52 2958.49,1247.35 2944.66,1247.35 2930.82,1261.18 2916.99,1247.35 2903.16,1247.35 2916.99,1233.52 2903.16,1219.68 ; 2903.16,1330.35 2958.49,1330.35 2958.49,1385.68 2903.16,1385.68 2903.16,1330.35 ; 2914.23,1341.42 2947.43,1341.42 2947.43,1374.62 2914.23,1374.62 2914.23,1341.42
  lines w12: 2853,546 5555.99,546 ; 2853,1417.5 5555.99,1417.5 ; 3191.01,421.5 3191.01,1542 ; 3523.17,421.5 3523.17,1542 ; 4159.65,421.5 4159.65,1542 ; 4418.85,421.5 4418.85,1542 ; 4794.09,421.5 4794.09,1542 ; 2853,421.5 5555.99,421.5 5555.99,1542 2853,1542 2853,421.5
  text "DRILL TABLE" at 2855,1605 h80
  text "Symbol" at 2927.7,1454.85 h72
  text "Quantity" at 3228.36,1454.85 h72
  text "Finished Hole Size" at 3560.52,1454.85 h72
  text "Plated" at 4197,1454.85 h72
  text "Hole Type" at 4456.2,1454.85 h72
  text "Drill Layer Pair" at 4831.44,1454.85 h72
  text "4" at 3228.36,1330.35 h60
  text "7.87mil (0.200mm)" at 3560.52,1330.35 h60
  text "PTH" at 4197,1330.35 h60
  text "Round" at 4456.2,1330.35 h60
  text "Top Layer - Bottom Layer" at 4831.44,1330.35 h60
  text "140" at 3228.36,1205.85 h60
  text "12.00mil (0.305mm)" at 3560.52,1205.85 h60
  text "PTH" at 4197,1205.85 h60
  text "Round" at 4456.2,1205.85 h60
  text "Top Layer - Bottom Layer" at 4831.44,1205.85 h60
  text "8" at 3228.36,1081.35 h60
  text "16.00mil (0.406mm)" at 3560.52,1081.35 h60
  text "PTH" at 4197,1081.35 h60
  text "Round" at 4456.2,1081.35 h60
  text "Top Layer - Bottom Layer" at 4831.44,1081.35 h60
  text "8" at 3228.36,956.85 h60
  text "27.56mil (0.700mm)" at 3560.52,956.85 h60
  text "PTH" at 4197,956.85 h60
  text "Round" at 4456.2,956.85 h60
  text "Top Layer - Bottom Layer" at 4831.44,956.85 h60
  text "3" at 3228.36,832.35 h60
  text "31.50mil (0.800mm)" at 3560.52,832.35 h60
  text "PTH" at 4197,832.35 h60
  text "Round" at 4456.2,832.35 h60
  text "Top Layer - Bottom Layer" at 4831.44,832.35 h60
  text "12" at 3228.36,707.85 h60
  text "35.43mil (0.900mm)" at 3560.52,707.85 h60
  text "PTH" at 4197,707.85 h60
  text "Round" at 4456.2,707.85 h60
  text "Top Layer - Bottom Layer" at 4831.44,707.85 h60
  text "16" at 3228.36,583.35 h60
  text "40.00mil (1.016mm)" at 3560.52,583.35 h60
  text "PTH" at 4197,583.35 h60
  text "Round" at 4456.2,583.35 h60
  text "Top Layer - Bottom Layer" at 4831.44,583.35 h60
  text "191 Total" at 3228.36,458.85 h60
  text "FOR 7.87MIL DRILL +0/-7.87MIL" at 2848,302 h80
  text "FOR 12MIL DRILL +0/-12MIL" at 2850,212 h80
  text "FOR 16MIL DRILL +0/-16MIL" at 2853,116 h80
  text "FOR PTH DRILL +/-3MIL" at 2853,19 h80
  text ".Layer_Name" at 523.85,-858.49 h60
M17 Embedded Cavity:
  text ".Layer_Name" at 523.85,-858.49 h60
M18 Embedded Assembly:
  text ".Layer_Name" at 523.85,-858.49 h60
M19 Embedded Keepout:
  text ".Layer_Name" at 523.85,-858.49 h60

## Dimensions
0,0 to 2165.35,0 on M2 Board Dimensions
0,0 to 0,1968.5 on M2 Board Dimensions
-53.15,-400 to 946.85,-400 on M2 Board Dimensions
